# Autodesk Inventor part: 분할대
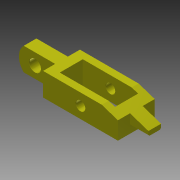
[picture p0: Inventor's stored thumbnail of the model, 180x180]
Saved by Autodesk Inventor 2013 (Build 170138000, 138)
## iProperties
Created: 2016-11
Part Number: 분할대
Material: 강철, 연강
Document SubType Name: Modeling
Designer: mduedu
Density: 1 g/cm^3
Author: mduedu
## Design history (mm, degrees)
sketch "스케치1"
  geometry: L1 (32.5, 16)-(-32.5, 16); L2 (-32.5, 16)-(-32.5, -16); L3 (-32.5, -16)-(32.5, -16); L4 (32.5, -16)-(32.5, 16); L5 (24, 10)-(-24, 10); L6 (-24, 10)-(-24, -10); L7 (-24, -10)-(24, -10); L8 (24, -10)-(24, 10); L9 (24, 0)-(-24, 0); L10 (0, -16)-(0, 16); 4 further points
  constraints: 20 end point, 7 midpoint, 4 parallel, 2 coincident, 2 horizontal, 2 perpendicular, 1 horizontal alignment
  dimensions: "d0" = 20 distance of L5.end L6.end; "d2" = 32 distance between parallel lines of L1 L3; "d3" = 48 distance of L5.start L5.end; "d4" = 65 distance of L1.start L1.end
extrude "돌출1" new body sketch "스케치1" distance "d5" = 20; taper "d6" = 0 deg
sketch "스케치2"
  geometry: L1 (0, 0)-(65, 0) reference; L2 (65, 0)-(65, 20) reference; L3 (0, 20)-(65, 20) reference; L4 (0, 0)-(0, 20) reference; L5 (32.5, 0)-(32.5, 20); C1 r 4 at (32.5, 10)
  constraints: 2 end point, 2 midpoint, 1 centre point
  dimensions: "d7" = 8 diameter of C1
extrude "돌출2" cut sketch "스케치2" stored distance "d8" = 20; taper "d9" = 0 deg
chamfer "모따기1" distance "d10" = 0.2; stored, may be unused: second distance "d11" = 2, angle "d12" = 45 deg
sketch "스케치3"
  geometry: L1 (-32.5, 0)-(-32.5, 20) reference; L2 (-32.5, 20)-(-59.798, 20); L3 (-64, 20)-(-64, 0); L4 (-64, 0)-(-59.798, 0); L5 (-32.5, 0)-(-32.5, 20); L6 (-59.798, 20)-(-64, 20); L7 (-59.798, 0)-(-32.5, 0); C1 r 4.2 at (0, 10) reference; C2 r 5 at (-50, 10); A1 r 14 centre (-50, 10) between (-59.798, 20) and (-59.798, 0); 1 further point
  constraints: 12 end point, 5 parallel, 2 centre point, 2 horizontal, 2 perpendicular, 2 point on circle, 1 coincident, 1 horizontal alignment, 1 tangent
  dimensions: "d13" = 64 distance from line of L3 C1.centre; "d14" = 14 radius of A1; "d15" = 10 diameter of C2
extrude "돌출3" join sketch "스케치3" stored distance "d16" = 11; taper "d17" = 0 deg
sketch "스케치4"
  geometry: L1 (32.5, 0)-(32.5, 20) reference; L2 (32.5, 20)-(48.5, 20); L3 (48.5, 20)-(48.5, 6); L4 (48.5, 6)-(32.5, 6); L5 (32.5, 6)-(32.5, 20); L6 (32.5, 0)-(-32.5, 0) reference; 1 further point
  constraints: 8 end point, 2 parallel, 1 horizontal, 1 perpendicular
  dimensions: "d18" = 16 distance of L1.end L2.end; "d19" = 6 distance between parallel lines of L4 L6
extrude "돌출4" join sketch "스케치4" stored distance "d20" = 11; taper "d21" = 0 deg
chamfer "모따기2" distance "d22" = 30; stored, may be unused: second distance "d23" = 10, angle "d24" = 45 deg
chamfer "모따기3" distance "d25" = 1; stored, may be unused: second distance "d26" = 10, angle "d27" = 45 deg
chamfer "모따기4" distance "d28" = 0.2; stored, may be unused: second distance "d29" = 10, angle "d30" = 45 deg
node "작업 평면1"
node "솔리드1"
node "투영된 루프1"
